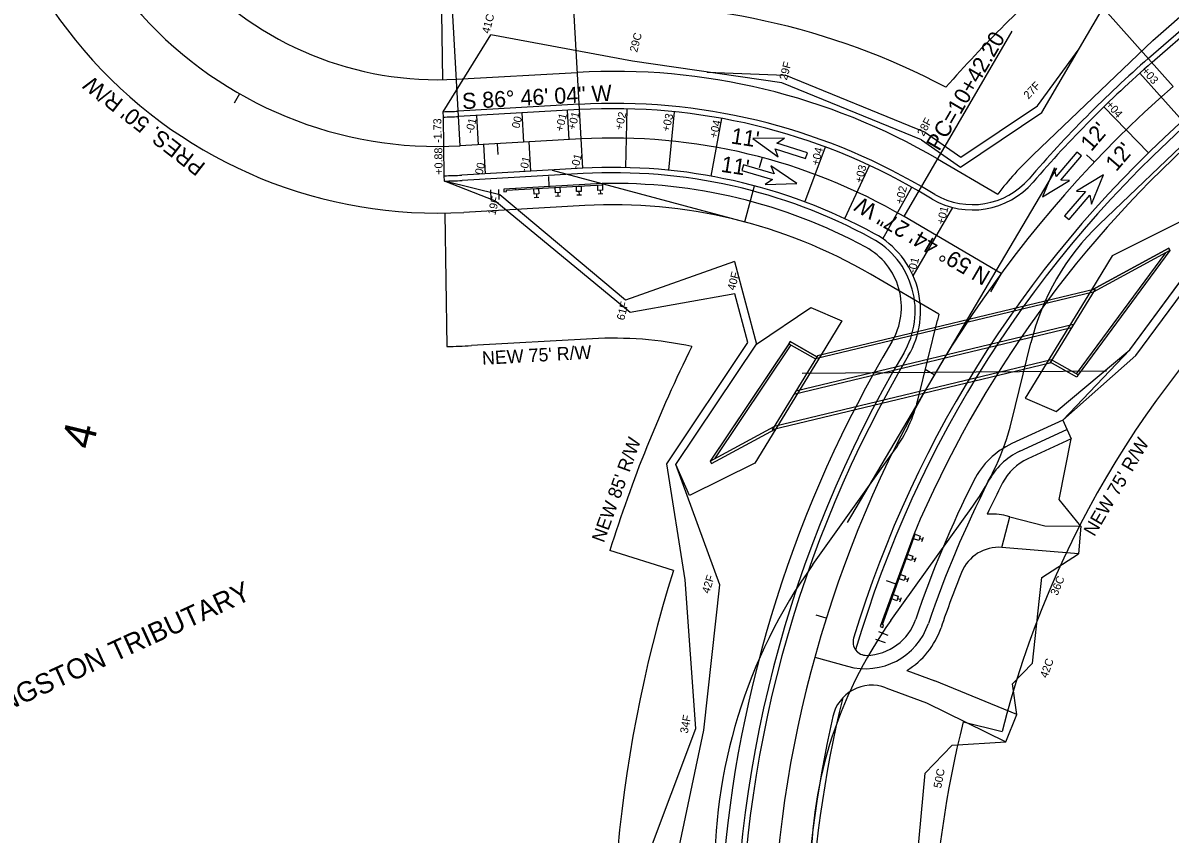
# Model space of a CAD drawing. Extents: x 1579440 to 1580937, y 1116374 to 1119566.
# Drawn here: x 1579773.5 to 1580203.4, y 1117456.1 to 1117760.1 of the extents above; entities that cross this region are included whole.
import ezdxf

# ---------------------------------------------------------------- set-up
doc = ezdxf.new("R2010")
doc.units = 0
for name, color, linetype in [('BR_CENTER LINES', 7, 'Continuous'), ('BR_CONCRETE', 7, 'Continuous'), ('Prop CMT Guardrail Graphics', 7, 'Continuous'), ('Prop CMT Pvmt Concrete', 7, 'Continuous'), ('Prop CMT Slope Grass', 7, 'Continuous'), ('RD_EX_RW_TX', 7, 'Continuous'), ('RD_EX_SU_Telecom', 7, 'Continuous'), ('RD_EX_VEG', 7, 'Continuous'), ('RD_HC_Cl', 7, 'Continuous'), ('RD_HC_Data', 7, 'Continuous'), ('RD_HC_Data_Tic', 7, 'Continuous'), ('RD_PD_ALT4_TX', 7, 'Continuous'), ('RD_PD_CstnLmt_TX', 7, 'Continuous'), ('RD_PD_DR_FlowCtrl', 7, 'Continuous'), ('RD_PD_PatLn1', 7, 'Continuous'), ('RD_Sketch1', 7, 'Continuous'), ('RD_XS_Base', 7, 'Continuous'), ('RD_XS_Binder', 7, 'Continuous'), ('RD_XS_EarthShd', 7, 'Continuous'), ('RD_XS_ExPaveRet', 7, 'Continuous'), ('RD_XS_Pave', 7, 'Continuous'), ('RD_XS_TX_Elev_EX', 7, 'Continuous'), ('RD_XS_TX_Slope', 7, 'Continuous')]:
    doc.layers.add(name, color=color, linetype=linetype)

# ---------------------------------------------------------------- blocks, each defined once
blk = doc.blocks.new('Guardrail_MT2_Leading_with_Buffer')
at = {"layer": 'RD_XS_Base'}
for p, q in [((17.52, 4.7), (15.77, 4.61)), ((16.72, 3.41), (16.65, 4.66)), ((25.51, 5.13), (23.76, 5.04)), ((24.7, 3.84), (24.64, 5.09)), ((38.94, 2.11), (38.74, 5.85)), ((41.94, 2.27), (41.74, 6.01)), ((1.55, 3.84), (-0.2, 3.74)), ((-0.13, 2.5), (1.61, 2.59)), ((-0.03, 0.5), (-0.13, 2.5)), ((35.92, 2.44), (-0.03, 0.5)), ((1.72, 0.59), (-0.03, 0.5)), ((-0.03, 0.5), (0, 0)), ((0, 0), (36.95, 2)), ((0.74, 2.54), (0.67, 3.79)), ((1.61, 2.59), (1.72, 0.59)), ((9.53, 4.27), (7.79, 4.18)), ((7.85, 2.93), (9.6, 3.02)), ((7.96, 0.93), (7.85, 2.93)), ((9.71, 1.03), (7.96, 0.93)), ((8.73, 2.98), (8.66, 4.22)), ((9.6, 3.02), (9.71, 1.03)), ((15.84, 3.36), (17.59, 3.45)), ((15.95, 1.36), (15.84, 3.36)), ((17.7, 1.46), (15.95, 1.36)), ((17.59, 3.45), (17.7, 1.46)), ((20.17, -2.67), (19.97, 1.08)), ((23.83, 3.79), (25.58, 3.89)), ((23.94, 1.79), (23.83, 3.79)), ((25.69, 1.89), (23.94, 1.79)), ((25.58, 3.89), (25.69, 1.89)), ((32.43, 2.25), (32.45, 1.75)), ((36.89, 3), (35.89, 2.94)), ((35.89, 2.94), (35.92, 2.44)), ((36.95, 2), (36.89, 3))]:
    blk.add_line(p, q, dxfattribs=at)

msp = doc.modelspace()

# ---------------------------------------------------------------- linework, layer by layer
at = {"layer": 'BR_CENTER LINES'}
for p, q in [((1580160.85, 1117705.68), (1580082.37, 1117572.94)), ((1580179.56, 1117629.56), (1580065.5, 1117628.75))]:
    msp.add_line(p, q, dxfattribs=at)
at = {"layer": 'BR_CONCRETE'}
for p, q in [((1580058.84, 1117716.84), (1580047.01, 1117716.81)), ((1580047.01, 1117716.81), (1580056.58, 1117709.85)), ((1580056.06, 1117715.06), (1580058.84, 1117716.84)), ((1580056.58, 1117709.85), (1580055.37, 1117712.92)), ((1580055.37, 1117712.92), (1580066.79, 1117709.23)), ((1580067.48, 1117711.37), (1580056.06, 1117715.06)), ((1580066.79, 1117709.23), (1580067.48, 1117711.37)), ((1580168.52, 1117711.7), (1580160.71, 1117702.58)), ((1580162.42, 1117701.12), (1580170.23, 1117710.23)), ((1580170.23, 1117710.23), (1580168.52, 1117711.7)), ((1580043.55, 1117706.9), (1580042.92, 1117704.74)), ((1580042.92, 1117704.74), (1580054.44, 1117701.38)), ((1580055.07, 1117703.54), (1580043.55, 1117706.9)), ((1580063.54, 1117699.9), (1580053.77, 1117706.58)), ((1580053.77, 1117706.58), (1580055.07, 1117703.54)), ((1580160.14, 1117705.83), (1580155.61, 1117694.9)), ((1580160.71, 1117702.58), (1580160.14, 1117705.83)), ((1580054.44, 1117701.38), (1580051.71, 1117699.52)), ((1580051.71, 1117699.52), (1580063.54, 1117699.9)), ((1580155.61, 1117694.9), (1580165.72, 1117701.05)), ((1580165.72, 1117701.05), (1580162.42, 1117701.12)), ((1580178.49, 1117703.16), (1580168.38, 1117697)), ((1580173.96, 1117692.22), (1580178.49, 1117703.16)), ((1580171.68, 1117696.94), (1580163.88, 1117687.83)), ((1580165.58, 1117686.36), (1580173.39, 1117695.48)), ((1580168.38, 1117697), (1580171.68, 1117696.94)), ((1580173.39, 1117695.48), (1580173.96, 1117692.22)), ((1580163.88, 1117687.83), (1580165.58, 1117686.36))]:
    msp.add_line(p, q, dxfattribs=at)
at = {"layer": 'Prop CMT Guardrail Graphics'}
for p, q in [((1580147.11, 1117599.56), (1580164.78, 1117607.7)), ((1580070.23, 1117522.38), (1580082.5, 1117518.99))]:
    msp.add_line(p, q, dxfattribs=at)
for centre, radius, start, end in [((1580494.33, 1117405.17), 440, 131.1901, 190.2447), ((1580157.57, 1117576.85), 25, 114.7328, 152.988), ((1580494.33, 1117405.17), 403, 152.988, 161.2024), ((1580089.16, 1117543.08), 25, 254.5511, 341.2024)]:
    msp.add_arc(centre, radius, start, end, dxfattribs=at)
at = {"layer": 'Prop CMT Pvmt Concrete'}
for p, q in [((1580163.18, 1117611.18), (1580144.16, 1117602.42)), ((1580163.18, 1117611.18), (1580166.38, 1117604.22)), ((1580166.38, 1117604.22), (1580150.07, 1117596.7)), ((1580140.38, 1117563.53), (1580143.39, 1117575.02)), ((1580143.39, 1117575.02), (1580141.94, 1117575.4)), ((1580143.39, 1117575.02), (1580156.49, 1117571.59)), ((1580156.49, 1117571.59), (1580169.96, 1117571.45)), ((1580169.96, 1117571.45), (1580169.07, 1117561.16)), ((1580169.07, 1117561.16), (1580140.38, 1117563.53)), ((1580104.74, 1117517.45), (1580115.25, 1117513.52)), ((1580096.9, 1117510.95), (1580112.16, 1117505.25)), ((1580146.02, 1117500.94), (1580115.25, 1117513.52)), ((1580112.16, 1117505.25), (1580141.83, 1117490.72)), ((1580141.83, 1117490.72), (1580146.02, 1117500.94))]:
    msp.add_line(p, q, dxfattribs=at)
for centre, radius, start, end in [((1580156.71, 1117575.17), 30, 114.7328, 153.2739), ((1580158.43, 1117578.54), 20, 114.7328, 152.7003), ((1580494.33, 1117405.17), 408, 153.2739, 161.2024), ((1580494.33, 1117405.17), 398, 152.7003, 154.5898), ((1580136.87, 1117556.06), 20, 75.3175, 95.8446), ((1580139.19, 1117548.58), 15, 85.4676, 158.0112), ((1580494.33, 1117405.17), 398, 158.0112, 161.2024), ((1580089.16, 1117543.08), 20, 271.6231, 341.2024), ((1580089.16, 1117543.08), 30, 301.2807, 341.2024), ((1580089.58, 1117528.09), 5, 163.1069, 271.6231), ((1580089.58, 1117528.09), 5, 216.5074, 271.6231), ((1580091.65, 1117496.9), 15, 69.5092, 167.1675)]:
    msp.add_arc(centre, radius, start, end, dxfattribs=at)
at = {"layer": 'Prop CMT Slope Grass'}
for p, q in [((1579971.77, 1117704.95), (1580044.05, 1117685.48)), ((1580044.05, 1117685.48), (1580047.66, 1117699.01))]:
    msp.add_line(p, q, dxfattribs=at)
at = {"layer": 'RD_EX_SU_Telecom'}
for p, q in [((1580201.66, 1117673.87), (1580168.27, 1117628.57)), ((1580203.38, 1117674.8), (1580169, 1117628.15)), ((1580202.91, 1117675.68), (1580174.18, 1117660.08)), ((1580203.38, 1117674.8), (1580174.55, 1117659.14)), ((1580203.38, 1117674.8), (1580202.91, 1117675.68)), ((1580175.28, 1117660.35), (1580071.24, 1117635.36)), ((1580175.28, 1117660.35), (1580158.29, 1117632.61)), ((1580174.55, 1117659.14), (1580070.5, 1117634.15)), ((1580173.91, 1117660.02), (1580156.92, 1117632.28)), ((1580166.42, 1117645.88), (1580062.38, 1117620.89)), ((1580167.16, 1117647.08), (1580063.12, 1117622.09)), ((1580060.5, 1117639.83), (1580031.07, 1117595.84)), ((1580061.23, 1117639.42), (1580032.64, 1117596.69)), ((1580060.5, 1117639.83), (1580061, 1117640.7)), ((1580060.5, 1117639.83), (1580070.5, 1117634.15)), ((1580061, 1117640.7), (1580071.03, 1117635.01)), ((1580071.24, 1117635.36), (1580054.25, 1117607.62)), ((1580072.62, 1117635.69), (1580055.63, 1117607.95)), ((1580158.29, 1117632.61), (1580054.25, 1117607.62)), ((1580159.03, 1117633.82), (1580054.99, 1117608.83)), ((1580168.51, 1117627.29), (1580158.51, 1117632.96)), ((1580169, 1117628.15), (1580159.03, 1117633.82)), ((1580169, 1117628.15), (1580168.51, 1117627.29)), ((1580031.07, 1117595.84), (1580054.99, 1117608.83)), ((1580031.54, 1117594.96), (1580055.35, 1117607.89)), ((1580031.07, 1117595.84), (1580031.54, 1117594.96))]:
    msp.add_line(p, q, dxfattribs=at)
at = {"layer": 'RD_HC_Cl'}
for p, q in [((1579982.65, 1117716.59), (1579937.3, 1117714.03)), ((1579982.65, 1117716.59), (1579937.3, 1117714.03)), ((1580140.15, 1117666.23), (1580103.69, 1117687.5)), ((1580140.15, 1117666.23), (1580103.69, 1117687.5))]:
    msp.add_line(p, q, dxfattribs=at)
for centre, radius, start, end in [((1579928.87, 1117863.31), 149.52, 171.1236, 273.2323), ((1579928.87, 1117863.31), 149.52, 171.1236, 273.2323), ((1579994.83, 1117500.9), 216.03, 59.7409, 93.2323), ((1579994.83, 1117500.9), 216.03, 59.7409, 93.2323)]:
    msp.add_arc(centre, radius, start, end, dxfattribs=at)
at = {"layer": 'RD_HC_Data'}
for p, q in [((1579982.65, 1117716.59), (1579975.95, 1117835.33)), ((1579937.3, 1117714.03), (1579930.72, 1117830.53)), ((1580204.6, 1117736.25), (1580127.53, 1117822.95)), ((1580103.69, 1117687.5), (1580144.19, 1117756.92))]:
    msp.add_line(p, q, dxfattribs=at)
at = {"layer": 'RD_HC_Data_Tic'}
for p, q in [((1579854.65, 1117733.51), (1579852.67, 1117730.04)), ((1579951.18, 1117714.81), (1579951.41, 1117710.82)), ((1580050.49, 1117709.64), (1580049.46, 1117705.77)), ((1580175.03, 1117707.91), (1580172.13, 1117710.66)), ((1580140.15, 1117666.23), (1580136.11, 1117659.32)), ((1580115.03, 1117628.18), (1580111.58, 1117630.2)), ((1580074.54, 1117536.98), (1580070.72, 1117538.17))]:
    msp.add_line(p, q, dxfattribs=at)
at = {"layer": 'RD_PD_ALT4_TX'}
for p, q in [((1580192.05, 1117741.22), (1580208.1, 1117723.38)), ((1579944.19, 1117714.41), (1579943.57, 1117725.4)), ((1579961.17, 1117715.37), (1579960.55, 1117726.36)), ((1579978.14, 1117716.33), (1579977.52, 1117727.31)), ((1579983.27, 1117705.6), (1579982.03, 1117727.57)), ((1579999.4, 1117705.88), (1579999.89, 1117727.87)), ((1580015.5, 1117704.89), (1580017.72, 1117726.77)), ((1580178.56, 1117728.58), (1580195.33, 1117711.41)), ((1580031.47, 1117702.63), (1580035.4, 1117724.28)), ((1579946.81, 1117703.55), (1579946.19, 1117714.53)), ((1579963.78, 1117704.5), (1579963.16, 1117715.49)), ((1580066.57, 1117692.97), (1580074.27, 1117713.58)), ((1580081.45, 1117686.74), (1580090.75, 1117706.68)), ((1580095.71, 1117679.21), (1580106.63, 1117698.5)), ((1580107.12, 1117665.33), (1580122.04, 1117690.9))]:
    msp.add_line(p, q, dxfattribs=at)
at = {"layer": 'RD_PD_DR_FlowCtrl'}
for points in [[(1580156.92, 1117632.28), (1580149.08, 1117619.49), (1580160.67, 1117614.49), (1580188.37, 1117637.58), (1580223.44, 1117685.16), (1580211.22, 1117687.59), (1580181.75, 1117672.81), (1580173.91, 1117660.02), (1580174.18, 1117660.08), (1580202.91, 1117675.68), (1580203.38, 1117674.8), (1580169, 1117628.15), (1580168.51, 1117627.29), (1580158.51, 1117632.96), (1580158.29, 1117632.61)], [(1580055.63, 1117607.95), (1580047.79, 1117595.16), (1580023.23, 1117583.05), (1580018.2, 1117594.58), (1580048.41, 1117639.74), (1580068.83, 1117653.49), (1580080.45, 1117648.48), (1580072.62, 1117635.69), (1580071.24, 1117635.36), (1580071.03, 1117635.01), (1580061, 1117640.7), (1580060.88, 1117640.5), (1580060.5, 1117639.83), (1580060.38, 1117639.63), (1580031.07, 1117595.84), (1580031.54, 1117594.96), (1580055.35, 1117607.89)], [(1580055.63, 1117607.95), (1580047.79, 1117595.16), (1580023.23, 1117583.05), (1580018.2, 1117594.58), (1580048.41, 1117639.74), (1580068.83, 1117653.49), (1580080.45, 1117648.48), (1580072.62, 1117635.69), (1580071.24, 1117635.36), (1580071.03, 1117635.01), (1580061, 1117640.7), (1580060.88, 1117640.5), (1580060.5, 1117639.83), (1580060.38, 1117639.63), (1580031.07, 1117595.84), (1580031.54, 1117594.96), (1580055.35, 1117607.89)]]:
    msp.add_lwpolyline(points, close=True, dxfattribs=at)
at = {"layer": 'RD_Sketch1'}
for p, q in [((1580195.35, 1117746.82), (1580277.39, 1117818.62)), ((1579981.92, 1117729.57), (1579936.57, 1117727.01)), ((1579931.04, 1117724.8), (1579931.01, 1117726.8)), ((1579983.38, 1117703.61), (1579938.04, 1117701.05)), ((1579931.41, 1117700.81), (1579931.38, 1117702.81)), ((1580115.24, 1117695.81), (1580110.24, 1117698.73))]:
    msp.add_line(p, q, dxfattribs=at)
for centre, radius, start, end in [((1580494.33, 1117405.17), 454, 131.1901, 139.2197), ((1579994.83, 1117500.9), 229.03, 59.7409, 93.2323), ((1579928.87, 1117863.31), 136.52, 270.8946, 273.2323), ((1580494.33, 1117405.17), 426, 131.1901, 163.6468), ((1579994.83, 1117500.9), 203.03, 61.5089, 93.2323), ((1579928.87, 1117863.31), 162.52, 270.8946, 273.2323), ((1580129.35, 1117720), 28, 239.7409, 319.2197), ((1580076.89, 1117652.1), 31, 329.3946, 61.5089), ((1580494.33, 1117405.17), 454, 149.3946, 181.614), ((1580494.33, 1117405.17), 426, 166.1452, 190.2447)]:
    msp.add_arc(centre, radius, start, end, dxfattribs=at)
at = {"layer": 'RD_XS_Base'}
for centre, radius, start, end in [((1580494.33, 1117405.17), 420, 131.1901, 157.0961), ((1579994.83, 1117500.9), 199.03, 61.6551, 91.2223), ((1580077.22, 1117653.63), 25.5, 329.2197, 61.6551), ((1580494.33, 1117405.17), 460, 149.2197, 175.5909)]:
    msp.add_arc(centre, radius, start, end, dxfattribs=at)
at = {"layer": 'RD_XS_Binder'}
for p, q in [((1580196.94, 1117753.53), (1580281.34, 1117827.39)), ((1580152.08, 1117710.69), (1580196.94, 1117753.53)), ((1579935.89, 1117738.99), (1579981.24, 1117741.55)), ((1580176.94, 1117684.65), (1580221.24, 1117726.96)), ((1580116.29, 1117709.09), (1580138.85, 1117695.93)), ((1579984.06, 1117691.63), (1579938.71, 1117689.07)), ((1580116.8, 1117650.91), (1580091.09, 1117665.9)), ((1580109.02, 1117619.23), (1580116.24, 1117648.72)), ((1580143.99, 1117610.66), (1580151.21, 1117640.16)), ((1580069.52, 1117557.1), (1580100.19, 1117599.99)), ((1580098.8, 1117536.16), (1580129.47, 1117579.05))]:
    msp.add_line(p, q, dxfattribs=at)
for centre, radius, start, end in [((1579928.87, 1117863.31), 174.52, 171.1236, 273.2323), ((1579928.87, 1117863.31), 124.52, 171.1236, 273.2323), ((1579994.83, 1117500.9), 241.03, 59.7409, 93.2323), ((1580240.27, 1117618.34), 127.69, 133.6822, 142.5831), ((1579994.83, 1117500.9), 191.03, 59.7409, 93.2323), ((1580240.27, 1117618.34), 91.69, 133.6822, 166.2368), ((1580240.27, 1117618.34), 127.69, 165.2247, 166.2368), ((1580054.66, 1117632.54), 55.96, 324.4316, 346.2368), ((1580054.66, 1117632.54), 91.96, 324.4316, 346.2368), ((1580229.76, 1117442.52), 197, 144.4316, 181.4941), ((1580229.76, 1117442.52), 161, 144.4316, 181.4941)]:
    msp.add_arc(centre, radius, start, end, dxfattribs=at)
at = {"layer": 'RD_XS_EarthShd'}
for p, q in [((1580196.66, 1117745.32), (1580278.71, 1117817.12)), ((1579931.38, 1117702.81), (1579931.04, 1117724.8)), ((1579982.03, 1117727.57), (1579936.68, 1117725.01)), ((1579983.27, 1117705.6), (1579937.92, 1117703.04)), ((1580114.23, 1117694.08), (1580109.24, 1117697))]:
    msp.add_line(p, q, dxfattribs=at)
for centre, radius, start, end in [((1580494.33, 1117405.17), 452, 131.1901, 139.2197), ((1579928.87, 1117863.31), 138.52, 270.8946, 273.2323), ((1579994.83, 1117500.9), 227.03, 59.7409, 93.2323), ((1580494.33, 1117405.17), 428, 131.1901, 163.1069), ((1579994.83, 1117500.9), 205.03, 61.5089, 93.2323), ((1579928.87, 1117863.31), 160.52, 270.8946, 273.2323), ((1580129.35, 1117720), 30, 239.7409, 319.2197), ((1580076.89, 1117652.1), 33, 329.3946, 61.5089), ((1580494.33, 1117405.17), 452, 149.3946, 180.4077), ((1580494.33, 1117405.17), 428, 167.1675, 190.2447)]:
    msp.add_arc(centre, radius, start, end, dxfattribs=at)
at = {"layer": 'RD_XS_ExPaveRet'}
for p, q in [((1580153.74, 1117729), (1580169.35, 1117750.41)), ((1580029.96, 1117741.68), (1580059.1, 1117740.45)), ((1580111.73, 1117718.95), (1580059.1, 1117740.45)), ((1580124.94, 1117709.71), (1580153.74, 1117729)), ((1580111.73, 1117718.95), (1580124.94, 1117709.71)), ((1580190.57, 1117635.5), (1580244.53, 1117708.32)), ((1579950.33, 1117693.41), (1579931.41, 1117700.81)), ((1580001.03, 1117651.52), (1579950.33, 1117693.41)), ((1580040.25, 1117658.58), (1580001.03, 1117651.52)), ((1580045.16, 1117640.27), (1580040.25, 1117658.58)), ((1580014.79, 1117594.89), (1580045.16, 1117640.27)), ((1580163.18, 1117611.18), (1580190.57, 1117635.5)), ((1580021.65, 1117551.4), (1580014.79, 1117594.89)), ((1580025.7, 1117495.64), (1580021.65, 1117551.4)), ((1580004.66, 1117439.88), (1580025.7, 1117495.64))]:
    msp.add_line(p, q, dxfattribs=at)
at = {"layer": 'RD_XS_Pave'}
for p, q in [((1579930.82, 1117738.8), (1579930.43, 1117763.8)), ((1579931.6, 1117688.81), (1579932.38, 1117638.82)), ((1579986.88, 1117641.71), (1579941.53, 1117639.15)), ((1580017.29, 1117554.95), (1579993.44, 1117562.44)), ((1580125.9, 1117498.23), (1580140.45, 1117494.56))]:
    msp.add_line(p, q, dxfattribs=at)
for centre, radius, start, end in [((1580494.33, 1117405.17), 500, 131.1901, 138.579), ((1579994.83, 1117500.9), 266.03, 62.0802, 93.2323), ((1580494.33, 1117405.17), 365, 131.1901, 165.8246), ((1579928.87, 1117863.31), 224.52, 270.8946, 273.2323), ((1579994.83, 1117500.9), 141.03, 77.9815, 93.2323), ((1580494.33, 1117405.17), 525, 153.5715, 162.5691), ((1580494.33, 1117405.17), 500, 162.5691, 188.6127), ((1580494.33, 1117405.17), 380, 165.8246, 190.2447)]:
    msp.add_arc(centre, radius, start, end, dxfattribs=at)
at = {"layer": 'RD_XS_TX_Elev_EX'}
for p, q in [((1580155.41, 1117726.51), (1580183.29, 1117774.31)), ((1579931.01, 1117726.8), (1579948.88, 1117755.58)), ((1580001.96, 1117745.69), (1579948.88, 1117755.58)), ((1580057.96, 1117737.67), (1580001.96, 1117745.69)), ((1580110.29, 1117716.3), (1580057.96, 1117737.67)), ((1580124.9, 1117706.07), (1580155.41, 1117726.51)), ((1580110.29, 1117716.3), (1580124.9, 1117706.07)), ((1579952.26, 1117695.71), (1579931.41, 1117700.81)), ((1579999.36, 1117656.23), (1579952.26, 1117695.71)), ((1580188.37, 1117637.58), (1580223.44, 1117685.16)), ((1580040.1, 1117670.68), (1579999.36, 1117656.23)), ((1580040.1, 1117670.68), (1580048.41, 1117639.74)), ((1580018.2, 1117594.58), (1580048.41, 1117639.74)), ((1580163.18, 1117611.18), (1580188.37, 1117637.58)), ((1580161.89, 1117581.53), (1580166.38, 1117604.22)), ((1580034.6, 1117549.51), (1580018.2, 1117594.58)), ((1580169.96, 1117571.45), (1580161.89, 1117581.53)), ((1580155.34, 1117552.26), (1580169.07, 1117561.16)), ((1580028.63, 1117495.02), (1580034.6, 1117549.51)), ((1580154.42, 1117544.41), (1580155.34, 1117552.26)), ((1580151.88, 1117520.21), (1580154.42, 1117544.41)), ((1580144.3, 1117512.45), (1580151.88, 1117520.21)), ((1580146.02, 1117500.94), (1580144.3, 1117512.45)), ((1580017.5, 1117441.94), (1580028.63, 1117495.02)), ((1580111.64, 1117479.01), (1580121.79, 1117489.4)), ((1580121.79, 1117489.4), (1580141.83, 1117490.72)), ((1580107.63, 1117434.99), (1580111.64, 1117479.01))]:
    msp.add_line(p, q, dxfattribs=at)

# ---------------------------------------------------------------- block references
at = {"layer": 'RD_PD_PatLn1', "rotation": -113.13190743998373}
msp.add_blockref('Guardrail_MT2_Leading_with_Buffer', (1580107.44, 1117568.63), dxfattribs=at)
at = {"layer": 'RD_XS_Base', "rotation": -179.86170939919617}
msp.add_blockref('Guardrail_MT2_Leading_with_Buffer', (1579990.59, 1117699.89), dxfattribs=at)

# ---------------------------------------------------------------- texts
at = {"layer": 'BR_CONCRETE'}
for s, rotation, p in [("11'", 351.2873, (1580038.58, 1117714.95)), ("12'", 49.4293, (1580173.87, 1117711.61)), ("12'", 49.4293, (1580183.22, 1117704.08)), ("11'", 351.2873, (1580034.84, 1117704.33))]:
    msp.add_text(s, height=6, rotation=rotation, dxfattribs=at).set_placement(p)
at = {"layer": 'RD_EX_RW_TX'}
msp.add_text("PRES. 50' R/W", height=6, rotation=142.1646, dxfattribs=at).set_placement((1579842.27, 1117707.06))
at = {"layer": 'RD_EX_VEG'}
for s, p in [('-1.73', (1579930.39, 1117715.17)), ('+0.88', (1579930.78, 1117703.22))]:
    msp.add_text(s, height=3, rotation=90.8946, dxfattribs=at).set_placement(p)
at = {"layer": 'RD_HC_Data'}
for s, height, rotation, p in [('PC=10+42.20', 6, 59.7409, (1580116.85, 1117711.74)), ('S 86%%d 46\' 04" W', 6, 3.2323, (1579938.21, 1117727.75)), ('N 59%%d 44\' 27" W', 6, 149.7409, (1580136.53, 1117666.62)), ('LANGSTON TRIBUTARY', 7.5, 24.6305, (1579755.17, 1117496.46))]:
    msp.add_text(s, height=height, rotation=rotation, dxfattribs=at).set_placement(p)
at = {"layer": 'RD_PD_ALT4_TX'}
for s, rotation, p in [('+03', 311.1901, (1580192.59, 1117741.94)), ('+04', 311.1901, (1580179.17, 1117729.34)), ('00', 76.2368, (1579959.49, 1117720.36)), ('+01', 76.2368, (1579975.8, 1117719.21)), ('+01', 76.2368, (1579980.49, 1117719.78)), ('+02', 76.2368, (1579998.08, 1117719.71)), ('+03', 76.2368, (1580015.68, 1117719.1)), ('-01', 76.2368, (1579942.13, 1117718.39)), ('+04', 76.2368, (1580033.53, 1117716.65)), ('+04', 76.2368, (1580071.73, 1117706.4)), ('00', 76.2368, (1579945.67, 1117703)), ('-01', 76.2368, (1579962.35, 1117704)), ('-01', 76.2368, (1579981.65, 1117705.01)), ('+03', 76.2368, (1580088.06, 1117699.86)), ('+02', 76.2368, (1580103.23, 1117691.94)), ('+01', 76.2368, (1580118.76, 1117684.32)), ('-01', 76.2368, (1580108, 1117666.18))]:
    msp.add_text(s, height=3, rotation=rotation, dxfattribs=at).set_placement(p)
at = {"layer": 'RD_PD_CstnLmt_TX'}
msp.add_text('4', height=12, rotation=76.2368, dxfattribs=at).set_placement((1579799.45, 1117599.83))
at = {"layer": 'RD_XS_Pave'}
for s, rotation, p in [("NEW 75' R/W", 3.2323, (1579945.67, 1117631.95)), ("NEW 85' R/W", 70.0782, (1579991.2, 1117565.04)), ("NEW 75' R/W", 59.6917, (1580175.03, 1117567.34))]:
    msp.add_text(s, height=5, rotation=rotation, dxfattribs=at).set_placement(p)
at = {"layer": 'RD_XS_TX_Slope'}
for s, rotation, p in [('41C', 74.8372, (1579948.27, 1117755.88)), ('29C', 75.3853, (1580003.65, 1117748.87)), ('29F', 75.0701, (1580059.77, 1117738.43)), ('27F', 46.5256, (1580150.33, 1117731.33)), ('28F', 61.809, (1580111.06, 1117717.39)), ('19F', 75.9522, (1579950.48, 1117687.86)), ('40F', 75.0701, (1580040.27, 1117659.66)), ('61F', 76.0456, (1579998.81, 1117648.46)), ('42F', 72.5691, (1580030.67, 1117546.06)), ('36C', 67.7248, (1580161.18, 1117545.26)), ('42C', 69.9658, (1580157.35, 1117514.37)), ('34F', 79.08, (1580022.61, 1117493.67)), ('50C', 79.08, (1580117.62, 1117473.13))]:
    msp.add_text(s, height=3, rotation=rotation, dxfattribs=at).set_placement(p)

doc.saveas('drawing.dxf')
